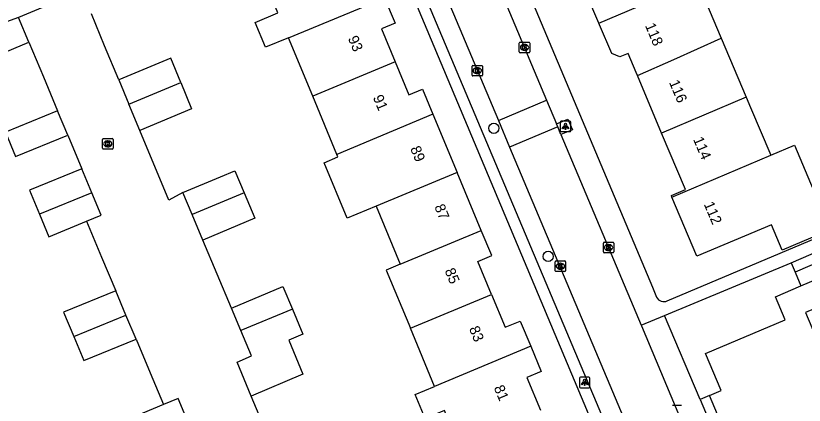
# Model space of a CAD drawing. Extents: x 157767 to 159171, y 387842 to 389425.
# Drawn here: x 158809.2 to 158884.5, y 388360 to 388397.2 of the extents above; entities that cross this region are included whole.
import ezdxf

# ---------------------------------------------------------------- set-up
doc = ezdxf.new("R2010")
doc.units = 0
for name, color, linetype in [('IMGEO_Boom', 7, 'Continuous'), ('IMGEO_Groenvoorziening', 7, 'Continuous'), ('IMGEO_Kolk', 7, 'Continuous'), ('IMGEO_Lichtpunt', 7, 'Continuous'), ('IMGEO_Pand', 7, 'Continuous'), ('IMGEO_Pand_nummerreeks', 7, 'Continuous'), ('IMGEO_Rijbaan_lokaal_open', 7, 'Continuous'), ('IMGEO_Voetpad_open', 7, 'Continuous')]:
    doc.layers.add(name, color=color, linetype=linetype)

msp = doc.modelspace()

# ---------------------------------------------------------------- linework, layer by layer
at = {"layer": 'IMGEO_Boom'}
for centre in [(158854.841, 388386.442), (158860.031, 388374.23)]:
    msp.add_circle(centre, 0.489, dxfattribs=at)
at = {"layer": 'IMGEO_Groenvoorziening'}
for points in [[(158883.599, 388372.731), (158884.156, 388371.409)], [(158875.426, 388360.972), (158874.528, 388360.59)]]:
    msp.add_lwpolyline(points, dxfattribs=at)
at = {"layer": 'IMGEO_Kolk'}
for p, q in [((158857.274, 388393.728), (158857.274, 388394.58)), ((158857.349, 388394.654), (158858.201, 388394.654)), ((158857.762, 388394.434), (158857.787, 388394.434)), ((158858.275, 388394.58), (158858.275, 388393.728)), ((158858.201, 388393.654), (158857.349, 388393.654)), ((158857.785, 388393.874), (158857.76, 388393.874)), ((158852.762, 388391.511), (158852.762, 388392.363)), ((158852.837, 388392.437), (158853.689, 388392.437)), ((158853.25, 388392.217), (158853.275, 388392.217)), ((158853.763, 388392.363), (158853.763, 388391.511)), ((158853.689, 388391.437), (158852.837, 388391.437)), ((158853.273, 388391.657), (158853.248, 388391.657)), ((158817.493, 388384.536), (158817.493, 388385.388)), ((158817.568, 388385.462), (158818.42, 388385.462)), ((158817.981, 388385.242), (158818.006, 388385.242)), ((158818.494, 388385.388), (158818.494, 388384.536)), ((158818.42, 388384.462), (158817.568, 388384.462)), ((158818.004, 388384.682), (158817.979, 388384.682)), ((158865.297, 388374.648), (158865.297, 388375.5)), ((158865.372, 388375.574), (158866.224, 388375.574)), ((158866.298, 388375.5), (158866.298, 388374.648)), ((158865.808, 388374.794), (158865.783, 388374.794)), ((158865.785, 388375.354), (158865.81, 388375.354)), ((158866.224, 388374.574), (158865.372, 388374.574)), ((158860.695, 388372.865), (158860.695, 388373.717)), ((158860.77, 388373.791), (158861.622, 388373.791)), ((158861.183, 388373.571), (158861.208, 388373.571)), ((158861.696, 388373.717), (158861.696, 388372.865)), ((158861.622, 388372.791), (158860.77, 388372.791)), ((158861.206, 388373.011), (158861.181, 388373.011)), ((158871.901, 388360.032), (158872.753, 388360.032))]:
    msp.add_line(p, q, dxfattribs=at)
for points in [[(158857.274, 388393.728), (158857.274, 388394.58)], [(158857.349, 388394.654), (158858.201, 388394.654)], [(158857.595, 388394.354), (158857.718, 388394.354), (158857.718, 388394.203), (158857.848, 388394.354), (158858.012, 388394.354), (158857.866, 388394.203), (158858.019, 388393.954), (158857.867, 388393.954), (158857.782, 388394.118), (158857.718, 388394.051), (158857.718, 388393.954), (158857.595, 388393.954), (158857.595, 388394.354)], [(158858.275, 388394.58), (158858.275, 388393.728)], [(158858.201, 388393.654), (158857.349, 388393.654)], [(158852.762, 388391.511), (158852.762, 388392.363)], [(158852.837, 388392.437), (158853.689, 388392.437)], [(158853.083, 388392.137), (158853.206, 388392.137), (158853.206, 388391.986), (158853.336, 388392.137), (158853.5, 388392.137), (158853.354, 388391.986), (158853.507, 388391.737), (158853.355, 388391.737), (158853.27, 388391.901), (158853.206, 388391.834), (158853.206, 388391.737), (158853.083, 388391.737), (158853.083, 388392.137)], [(158853.763, 388392.363), (158853.763, 388391.511)], [(158853.689, 388391.437), (158852.837, 388391.437)], [(158817.493, 388384.536), (158817.493, 388385.388)], [(158817.568, 388385.462), (158818.42, 388385.462)], [(158818.494, 388385.388), (158818.494, 388384.536)], [(158818.42, 388384.462), (158817.568, 388384.462)], [(158817.814, 388385.162), (158817.937, 388385.162), (158817.937, 388385.011), (158818.067, 388385.162), (158818.231, 388385.162), (158818.085, 388385.011), (158818.238, 388384.762), (158818.086, 388384.762), (158818.001, 388384.926), (158817.937, 388384.859), (158817.937, 388384.762), (158817.814, 388384.762), (158817.814, 388385.162)], [(158865.297, 388374.648), (158865.297, 388375.5)], [(158865.372, 388375.574), (158866.224, 388375.574)], [(158866.298, 388375.5), (158866.298, 388374.648)], [(158865.618, 388375.274), (158865.741, 388375.274), (158865.741, 388375.123), (158865.871, 388375.274), (158866.035, 388375.274), (158865.889, 388375.123), (158866.042, 388374.874), (158865.89, 388374.874), (158865.805, 388375.038), (158865.741, 388374.971), (158865.741, 388374.874), (158865.618, 388374.874), (158865.618, 388375.274)], [(158866.224, 388374.574), (158865.372, 388374.574)], [(158860.695, 388372.865), (158860.695, 388373.717)], [(158860.77, 388373.791), (158861.622, 388373.791)], [(158861.016, 388373.491), (158861.139, 388373.491), (158861.139, 388373.34), (158861.269, 388373.491), (158861.433, 388373.491), (158861.287, 388373.34), (158861.44, 388373.091), (158861.288, 388373.091), (158861.203, 388373.255), (158861.139, 388373.188), (158861.139, 388373.091), (158861.016, 388373.091), (158861.016, 388373.491)], [(158861.696, 388373.717), (158861.696, 388372.865)], [(158861.622, 388372.791), (158860.77, 388372.791)], [(158871.901, 388360.032), (158872.753, 388360.032)]]:
    msp.add_lwpolyline(points, dxfattribs=at)
for centre, start, end in [((158857.351, 388394.578), 91.55205, 178.44795), ((158857.351, 388394.578), 91.55205, 178.44795), ((158858.199, 388394.578), 1.55205, 88.44795), ((158858.199, 388394.578), 1.55205, 88.44795), ((158857.351, 388393.73), 181.55205, 268.44795), ((158857.351, 388393.73), 181.55205, 268.44795), ((158858.199, 388393.73), 271.55205, 358.44795), ((158858.199, 388393.73), 271.55205, 358.44795), ((158852.839, 388392.361), 91.55205, 178.44795), ((158852.839, 388392.361), 91.55205, 178.44795), ((158853.687, 388392.361), 1.55205, 88.44795), ((158853.687, 388392.361), 1.55205, 88.44795), ((158852.839, 388391.513), 181.55205, 268.44795), ((158852.839, 388391.513), 181.55205, 268.44795), ((158853.687, 388391.513), 271.55205, 358.44795), ((158853.687, 388391.513), 271.55205, 358.44795), ((158817.57, 388385.386), 91.55205, 178.44795), ((158817.57, 388385.386), 91.55205, 178.44795), ((158818.418, 388385.386), 1.55205, 88.44795), ((158818.418, 388385.386), 1.55205, 88.44795), ((158817.57, 388384.538), 181.55205, 268.44795), ((158817.57, 388384.538), 181.55205, 268.44795), ((158818.418, 388384.538), 271.55205, 358.44795), ((158818.418, 388384.538), 271.55205, 358.44795), ((158865.374, 388375.498), 91.55205, 178.44795), ((158865.374, 388375.498), 91.55205, 178.44795), ((158866.222, 388375.498), 1.55205, 88.44795), ((158866.222, 388375.498), 1.55205, 88.44795), ((158865.374, 388374.65), 181.55205, 268.44795), ((158865.374, 388374.65), 181.55205, 268.44795), ((158866.222, 388374.65), 271.55205, 358.44795), ((158866.222, 388374.65), 271.55205, 358.44795), ((158860.772, 388373.715), 91.55205, 178.44795), ((158860.772, 388373.715), 91.55205, 178.44795), ((158861.62, 388373.715), 1.55205, 88.44795), ((158861.62, 388373.715), 1.55205, 88.44795), ((158860.772, 388372.867), 181.55205, 268.44795), ((158860.772, 388372.867), 181.55205, 268.44795), ((158861.62, 388372.867), 271.55205, 358.44795), ((158861.62, 388372.867), 271.55205, 358.44795)]:
    msp.add_arc(centre, 0.0765, start, end, dxfattribs=at)
for centre, major_axis, ratio, start_param, end_param in [((158857.761, 388394.154), (-0.387, 0.002), 0.722429, 4.712389, 7.853982), ((158857.786, 388394.154), (-0.39, 0.002), 0.717154, 1.570796, 4.712389), ((158853.249, 388391.937), (-0.387, 0.002), 0.722429, 4.712389, 7.853982), ((158853.274, 388391.937), (-0.39, 0.002), 0.717154, 1.570796, 4.712389), ((158817.98, 388384.962), (-0.387, 0.002), 0.722429, 4.712389, 7.853982), ((158818.005, 388384.962), (-0.39, 0.002), 0.717154, 1.570796, 4.712389), ((158865.784, 388375.074), (-0.387, 0.002), 0.722429, 4.712389, 7.853982), ((158865.809, 388375.074), (-0.39, 0.002), 0.717154, 1.570796, 4.712389), ((158861.182, 388373.291), (-0.387, 0.002), 0.722429, 4.712389, 7.853982), ((158861.207, 388373.291), (-0.39, 0.002), 0.717154, 1.570796, 4.712389)]:
    msp.add_ellipse(centre, major_axis=major_axis, ratio=ratio, start_param=start_param, end_param=end_param, dxfattribs=at)
at = {"layer": 'IMGEO_Lichtpunt'}
for p, q in [((158861.191, 388387.027), (158861.191, 388386.22)), ((158861.191, 388387.027), (158861.191, 388386.22)), ((158862.093, 388387.122), (158861.285, 388387.122)), ((158862.093, 388387.122), (158861.285, 388387.122)), ((158862.187, 388386.22), (158862.187, 388387.027)), ((158862.187, 388386.22), (158862.187, 388387.027)), ((158861.285, 388386.126), (158862.093, 388386.126)), ((158861.285, 388386.126), (158862.093, 388386.126)), ((158863.913, 388362.7), (158863.105, 388362.7)), ((158863.913, 388362.7), (158863.105, 388362.7)), ((158863.011, 388362.605), (158863.011, 388361.798)), ((158863.011, 388362.605), (158863.011, 388361.798)), ((158864.007, 388361.798), (158864.007, 388362.605)), ((158864.007, 388361.798), (158864.007, 388362.605)), ((158863.105, 388361.704), (158863.913, 388361.704)), ((158863.105, 388361.704), (158863.913, 388361.704))]:
    msp.add_line(p, q, dxfattribs=at)
for points in [[(158861.565, 388386.691), (158861.604, 388386.663), (158861.416, 388386.401), (158861.378, 388386.428), (158861.565, 388386.691)], [(158861.667, 388386.643), (158861.714, 388386.643), (158861.714, 388386.321), (158861.667, 388386.321), (158861.667, 388386.643)], [(158861.777, 388386.663), (158861.815, 388386.69), (158862.002, 388386.428), (158861.963, 388386.4), (158861.777, 388386.663)], [(158863.385, 388362.269), (158863.424, 388362.241), (158863.236, 388361.979), (158863.198, 388362.006), (158863.385, 388362.269)], [(158863.487, 388362.221), (158863.534, 388362.221), (158863.534, 388361.899), (158863.487, 388361.899), (158863.487, 388362.221)], [(158863.597, 388362.241), (158863.635, 388362.268), (158863.822, 388362.006), (158863.783, 388361.978), (158863.597, 388362.241)]]:
    msp.add_lwpolyline(points, dxfattribs=at)
for centre in [(158861.69, 388386.825), (158863.51, 388362.403)]:
    msp.add_circle(centre, 0.0994, dxfattribs=at)
for centre, start, end in [((158861.285, 388387.027), 90, 180), ((158861.285, 388387.027), 90, 180), ((158862.093, 388387.027), 0, 90), ((158862.093, 388387.027), 0, 90), ((158861.285, 388386.22), 180, 270), ((158861.285, 388386.22), 180, 270), ((158862.093, 388386.22), 270, 0), ((158862.093, 388386.22), 270, 360), ((158863.105, 388362.605), 90, 180), ((158863.105, 388362.605), 90, 180), ((158863.913, 388362.605), 0, 90), ((158863.913, 388362.605), 0, 90), ((158863.105, 388361.798), 180, 270), ((158863.105, 388361.798), 180, 270), ((158863.913, 388361.798), 270, 0), ((158863.913, 388361.798), 270, 360)]:
    msp.add_arc(centre, 0.0946, start, end, dxfattribs=at)
at = {"layer": 'IMGEO_Pand'}
for points in [[(158864.872, 388396.463), (158862.463, 388402.156)], [(158835.23, 388395.077), (158833.04, 388394.167), (158832.049, 388396.551), (158834.238, 388397.46), (158832.917, 388400.635)], [(158864.872, 388396.463), (158874.252, 388400.478)], [(158874.252, 388400.478), (158876.559, 388395.026)], [(158835.23, 388395.077), (158844.419, 388398.895)], [(158844.419, 388398.895), (158845.43, 388396.466), (158844.131, 388395.925), (158845.438, 388392.785)], [(158811.772, 388397.955), (158809.485, 388397.005)], [(158808.311, 388396.589), (158804.533, 388395.019), (158805.533, 388392.601), (158810.468, 388394.652)], [(158809.485, 388397.005), (158808.311, 388396.589)], [(158810.468, 388394.652), (158809.485, 388397.005)], [(158868.545, 388391.469), (158868.423, 388391.756), (158867.652, 388393.579), (158866.873, 388393.249), (158866.099, 388393.563), (158864.93, 388396.325), (158864.872, 388396.463)], [(158837.551, 388389.501), (158835.23, 388395.077)], [(158868.545, 388391.469), (158872.03, 388393.016), (158876.559, 388395.026)], [(158876.559, 388395.026), (158878.935, 388389.41)], [(158824.956, 388390.807), (158823.998, 388393.132), (158819.038, 388391.067)], [(158845.438, 388392.785), (158837.551, 388389.501)], [(158845.438, 388392.785), (158846.745, 388389.643), (158848.036, 388390.18), (158849.034, 388387.783)], [(158870.861, 388385.994), (158868.545, 388391.469)], [(158819.038, 388391.067), (158820.001, 388388.748)], [(158820.001, 388388.748), (158824.956, 388390.807)], [(158824.956, 388390.807), (158825.983, 388388.314), (158821.042, 388386.242)], [(158839.856, 388383.961), (158837.551, 388389.501)], [(158878.935, 388389.41), (158870.861, 388385.994)], [(158878.935, 388389.41), (158879.351, 388388.427), (158881.278, 388383.873)], [(158821.042, 388386.242), (158820.001, 388388.748)], [(158813.206, 388388.096), (158808.238, 388386.064), (158809.192, 388383.759), (158814.168, 388385.794)], [(158814.168, 388385.794), (158813.206, 388388.096)], [(158849.034, 388387.783), (158839.856, 388383.961)], [(158849.034, 388387.783), (158851.34, 388382.241)], [(158871.848, 388379.884), (158871.788, 388380.026), (158873.144, 388380.6), (158870.861, 388385.994)], [(158881.278, 388383.873), (158883.553, 388384.835), (158886.962, 388376.775), (158882.375, 388374.834), (158881.353, 388377.249), (158874.237, 388374.237), (158871.848, 388379.884)], [(158843.608, 388379.022), (158840.835, 388377.868), (158838.634, 388383.155), (158839.962, 388383.707), (158839.856, 388383.961)], [(158871.848, 388379.884), (158881.278, 388383.873)], [(158815.505, 388382.592), (158810.521, 388380.55), (158811.477, 388378.24)], [(158816.469, 388380.285), (158815.505, 388382.592)], [(158825.171, 388380.319), (158828.743, 388381.817), (158830.116, 388382.393), (158831.004, 388380.276)], [(158851.34, 388382.241), (158843.608, 388379.022)], [(158853.646, 388376.701), (158851.34, 388382.241)], [(158816.469, 388380.285), (158811.477, 388378.24)], [(158815.958, 388377.594), (158817.351, 388378.173), (158816.469, 388380.285)], [(158826.053, 388378.214), (158825.171, 388380.319)], [(158831.004, 388380.276), (158826.053, 388378.214)], [(158831.004, 388380.276), (158832.016, 388377.863), (158827.07, 388375.789)], [(158843.608, 388379.022), (158845.914, 388373.482)], [(158811.477, 388378.24), (158812.362, 388376.1), (158815.958, 388377.594)], [(158827.07, 388375.789), (158826.053, 388378.214)], [(158845.914, 388373.482), (158853.646, 388376.701)], [(158854.617, 388370.604), (158853.309, 388373.746), (158854.644, 388374.302), (158853.646, 388376.701)], [(158884.156, 388371.409), (158892.445, 388374.91), (158893.417, 388372.607), (158884.594, 388368.881), (158894.893, 388344.493), (158903.706, 388348.215), (158904.663, 388345.949), (158893.85, 388341.383), (158892.902, 388343.626), (158885.364, 388340.443), (158883.881, 388343.954), (158882.795, 388343.494), (158875.426, 388360.972)], [(158845.914, 388373.482), (158844.569, 388372.922), (158846.875, 388367.38)], [(158818.759, 388370.939), (158813.781, 388368.904), (158814.743, 388366.596)], [(158819.729, 388368.635), (158818.759, 388370.939)], [(158829.792, 388369.303), (158834.711, 388371.366), (158835.62, 388369.197)], [(158875.426, 388360.972), (158876.531, 388361.438), (158875.041, 388364.966), (158882.649, 388368.179), (158881.72, 388370.38), (158884.156, 388371.409)], [(158846.875, 388367.38), (158854.617, 388370.604)], [(158854.617, 388370.604), (158855.924, 388367.464), (158857.361, 388368.062), (158858.364, 388365.652)], [(158830.696, 388367.147), (158829.792, 388369.303)], [(158835.62, 388369.197), (158830.696, 388367.147)], [(158835.62, 388369.197), (158836.623, 388366.806), (158835.281, 388366.243), (158836.618, 388362.988), (158831.693, 388360.899)], [(158814.743, 388366.596), (158819.729, 388368.635)], [(158820.699, 388366.331), (158819.729, 388368.635)], [(158831.693, 388360.899), (158830.35, 388364.151), (158831.704, 388364.743), (158830.696, 388367.147)], [(158849.185, 388361.83), (158846.875, 388367.38)], [(158814.743, 388366.596), (158815.705, 388364.288), (158820.699, 388366.331)], [(158858.364, 388365.652), (158849.185, 388361.83)], [(158858.364, 388365.652), (158859.366, 388363.244), (158858.005, 388362.678), (158859.304, 388359.557)], [(158851.486, 388356.302), (158850.141, 388359.534), (158848.282, 388358.76), (158847.326, 388361.056), (158849.185, 388361.83)], [(158825.768, 388358.162), (158824.716, 388360.68), (158823.321, 388360.1)], [(158823.321, 388360.1), (158819.744, 388358.613), (158819.839, 388358.384), (158820.78, 388356.121)]]:
    msp.add_lwpolyline(points, dxfattribs=at)
at = {"layer": 'IMGEO_Rijbaan_lokaal_open'}
for points in [[(158847.266, 388419.093), (158859.88, 388389.119)], [(158842.313, 388417.957), (158855.282, 388387.184)], [(158819.038, 388391.067), (158817.695, 388394.299), (158816.429, 388397.347)], [(158810.468, 388394.652), (158811.851, 388391.341), (158813.206, 388388.096)], [(158855.282, 388387.184), (158859.88, 388389.119)], [(158859.88, 388389.119), (158860.832, 388386.857)], [(158855.282, 388387.184), (158856.353, 388384.641)], [(158860.95, 388386.576), (158860.832, 388386.857)], [(158825.171, 388380.319), (158823.826, 388379.588), (158821.042, 388386.242)], [(158860.95, 388386.576), (158856.353, 388384.641)], [(158861.255, 388385.851), (158860.95, 388386.576)], [(158814.168, 388385.794), (158815.505, 388382.592)], [(158861.255, 388385.851), (158868.903, 388367.676)], [(158856.353, 388384.641), (158870.521, 388351.022)], [(158815.958, 388377.594), (158817.401, 388374.166), (158818.759, 388370.939)], [(158829.792, 388369.303), (158827.07, 388375.789)], [(158868.903, 388367.676), (158868.934, 388367.603), (158876.369, 388349.934), (158877.15, 388348.079), (158873.925, 388339.494)], [(158820.699, 388366.331), (158822.05, 388363.12), (158823.321, 388360.1)], [(158833.035, 388357.646), (158831.693, 388360.899)]]:
    msp.add_lwpolyline(points, dxfattribs=at)
at = {"layer": 'IMGEO_Voetpad_open'}
for points in [[(158838.652, 388419.211), (158868.881, 388347.284), (158853.592, 388340.805), (158843.883, 388336.691), (158834.401, 388332.713), (158827.967, 388330.084)], [(158870.521, 388351.022), (158868.839, 388350.328), (158840.615, 388417.244), (158842.313, 388417.957)], [(158860.985, 388401.48), (158857.849, 388400.164), (158869.979, 388371.299), (158870.387, 388370.328)], [(158860.832, 388386.857), (158861.919, 388387.315), (158862.342, 388386.309), (158861.255, 388385.851)], [(158871.4, 388369.985), (158903.135, 388383.377)], [(158883.228, 388373.611), (158891.082, 388377.002)], [(158892.006, 388376.345), (158883.599, 388372.731)], [(158871.139, 388368.602), (158883.228, 388373.611)], [(158883.228, 388373.611), (158883.599, 388372.731)], [(158868.903, 388367.676), (158871.139, 388368.602)], [(158874.528, 388360.59), (158871.139, 388368.602)], [(158874.528, 388360.59), (158878.652, 388350.839), (158884.896, 388336.062)]]:
    msp.add_lwpolyline(points, dxfattribs=at)
msp.add_arc((158871.077, 388370.7), 0.784, 208.30005, 294.28793, dxfattribs=at)

# ---------------------------------------------------------------- texts
at = {"layer": 'IMGEO_Pand_nummerreeks'}
for s, rotation, p in [('118', 292.93566, (158869.257, 388396.252)), ('93', 292.89075, (158840.898, 388395.025)), ('116', 292.93566, (158871.553, 388390.825)), ('91', 292.89075, (158843.277, 388389.391)), ('114', 292.93566, (158873.85, 388385.396)), ('89', 292.59563, (158846.842, 388384.515)), ('87', 292.59724, (158849.148, 388378.974)), ('112', 292.92956, (158874.866, 388379.217)), ('85', 292.79778, (158850.128, 388372.87)), ('83', 292.79549, (158852.452, 388367.341)), ('81', 292.79549, (158854.821, 388361.706))]:
    msp.add_text(s, height=1, rotation=rotation, dxfattribs=at).set_placement(p)

doc.saveas('drawing.dxf')
